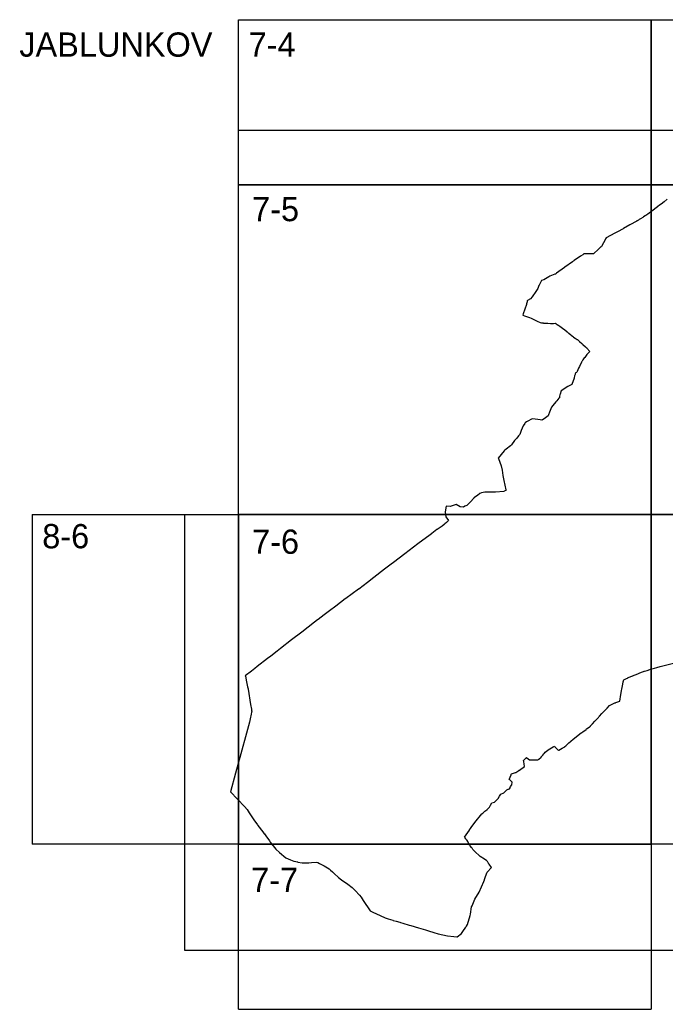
# Model space of a CAD drawing. Extents: x -449577 to -436680, y -1132317 to -1125726.
# Drawn here: x -437175.4 to -436931, y -1130193.4 to -1129818.4 of the extents above; entities that cross this region are included whole.
import ezdxf

# ---------------------------------------------------------------- set-up
doc = ezdxf.new("R2010")
doc.units = 0
for name, color, linetype in [('Vrstva 1', 7, 'Continuous'), ('Vrstva 10', 7, 'Continuous'), ('Vrstva 4', 7, 'Continuous')]:
    doc.layers.add(name, color=color, linetype=linetype)

msp = doc.modelspace()

# ---------------------------------------------------------------- linework, layer by layer
at = {"layer": 'Vrstva 1'}
for points in [[(-436930.19, -1129886.4), (-436931.4, -1129887.36), (-436931.4, -1129887.36), (-436932.55, -1129888.23), (-436933.12, -1129888.66), (-436933.7, -1129889.1), (-436933.86, -1129889.22), (-436935.99, -1129890.86), (-436937.06, -1129891.68), (-436937.53, -1129892.02), (-436938.29, -1129892.53), (-436938.54, -1129892.69), (-436939.13, -1129893.08), (-436939.17, -1129893.11), (-436939.38, -1129893.25), (-436940.29, -1129893.85), (-436940.3, -1129893.85), (-436940.77, -1129894.11), (-436940.92, -1129894.19), (-436941.1, -1129894.29), (-436941.56, -1129894.54), (-436941.74, -1129894.65), (-436941.9, -1129894.74), (-436942, -1129894.8), (-436942.24, -1129894.94), (-436943.9, -1129895.88), (-436944.07, -1129895.97), (-436944.3, -1129896.1), (-436946.77, -1129897.5), (-436946.89, -1129897.57), (-436949, -1129898.7), (-436950.02, -1129899.25), (-436953.36, -1129901.06), (-436953.53, -1129901.36), (-436953.59, -1129901.47), (-436954.37, -1129902.93), (-436955.05, -1129904.25), (-436955.19, -1129904.38), (-436955.28, -1129904.46), (-436956.42, -1129905.5), (-436957.93, -1129906.88), (-436958.1, -1129907.03), (-436958.1, -1129907.04), (-436958.57, -1129907.05), (-436961.76, -1129907.14), (-436961.77, -1129907.14), (-436962.2, -1129907.43), (-436963.03, -1129908), (-436965.5, -1129909.66), (-436965.54, -1129909.68), (-436965.78, -1129909.86), (-436966.05, -1129910.06), (-436969.03, -1129912.19), (-436969.1, -1129912.24), (-436972.1, -1129914.42), (-436972.57, -1129914.76), (-436972.73, -1129914.82), (-436974.67, -1129915.54), (-436974.68, -1129915.54), (-436975.07, -1129915.78), (-436976.95, -1129916.94), (-436977.87, -1129917.15), (-436978.12, -1129917.66), (-436978.88, -1129919.17), (-436978.89, -1129919.18), (-436978.96, -1129919.44), (-436979.16, -1129920.28), (-436979.99, -1129921.39), (-436981.36, -1129923.34), (-436981.92, -1129924.15), (-436981.95, -1129924.17), (-436983.11, -1129924.81), (-436983.21, -1129924.87), (-436983.28, -1129925.26), (-436983.43, -1129926.07), (-436983.48, -1129926.26), (-436984.77, -1129929.84), (-436984.94, -1129930.32), (-436984.91, -1129930.31), (-436984.89, -1129930.3), (-436984.21, -1129930.56), (-436982.4, -1129931.22), (-436981.78, -1129931.51), (-436979.49, -1129932.59), (-436979.47, -1129932.59), (-436978.31, -1129933.06), (-436977.84, -1129933.24), (-436977.81, -1129933.25), (-436977.38, -1129933.28), (-436977.24, -1129933.29), (-436977.02, -1129933.31), (-436975.42, -1129933.41), (-436974.38, -1129933.48), (-436973.33, -1129933.45), (-436972.49, -1129933.42), (-436972.48, -1129933.42), (-436972.2, -1129933.57), (-436971.83, -1129933.83), (-436971.28, -1129934.21), (-436970.89, -1129934.49), (-436969.33, -1129935.63), (-436969.16, -1129935.75), (-436968.05, -1129936.67), (-436967.66, -1129936.99), (-436967.48, -1129937.14), (-436966.73, -1129937.75), (-436966.46, -1129937.98), (-436965.86, -1129938.47), (-436965.64, -1129938.65), (-436965, -1129939.07), (-436964.25, -1129939.57), (-436964.22, -1129939.59), (-436963.46, -1129940.27), (-436962.58, -1129941.05), (-436962.14, -1129941.43), (-436961.13, -1129942.32), (-436960.87, -1129942.55), (-436960.82, -1129942.6), (-436960.72, -1129942.7), (-436960.71, -1129942.71), (-436960.62, -1129942.81), (-436960.59, -1129942.84), (-436959.54, -1129944.07), (-436959.55, -1129944.08), (-436959.99, -1129944.57), (-436960.05, -1129944.64), (-436960.62, -1129945.27), (-436961.44, -1129946.33), (-436961.61, -1129946.54), (-436962.17, -1129947.26), (-436962.47, -1129947.79), (-436962.49, -1129947.83), (-436962.5, -1129947.85), (-436962.63, -1129948.13), (-436963.43, -1129949.8), (-436963.74, -1129950.44), (-436964.36, -1129951.73), (-436964.47, -1129951.97), (-436964.48, -1129951.97), (-436964.52, -1129952), (-436964.81, -1129952.2), (-436964.89, -1129952.24), (-436964.94, -1129952.34), (-436965.03, -1129952.54), (-436965.12, -1129952.82), (-436965.29, -1129953.38), (-436965.3, -1129953.4), (-436965.42, -1129953.9), (-436965.44, -1129953.97), (-436965.43, -1129954.03), (-436965.42, -1129954.11), (-436965.42, -1129954.18), (-436965.43, -1129954.23), (-436966.31, -1129956.56), (-436966.33, -1129956.61), (-436966.35, -1129956.65), (-436966.36, -1129956.66), (-436967.06, -1129956.96), (-436967.31, -1129957.07), (-436967.78, -1129957.31), (-436970.39, -1129959), (-436970.39, -1129959), (-436970.76, -1129960.31), (-436970.84, -1129960.57), (-436970.95, -1129960.99), (-436971.01, -1129961.2), (-436971.01, -1129961.21), (-436971, -1129961.21), (-436970.83, -1129961.37), (-436970.84, -1129961.38), (-436971.2, -1129961.77), (-436972, -1129962.77), (-436972.01, -1129962.78), (-436972.22, -1129963.03), (-436972.22, -1129963.04), (-436972.34, -1129963.19), (-436973.5, -1129964.54), (-436974.04, -1129965.17), (-436974.8, -1129967.12), (-436975.18, -1129968.14), (-436975.31, -1129968.49), (-436976.84, -1129969.59), (-436977.46, -1129970.03), (-436977.64, -1129970.07), (-436977.66, -1129970.07), (-436978.29, -1129969.98), (-436981.13, -1129969.56), (-436981.62, -1129969.8), (-436982.95, -1129970.44), (-436983.49, -1129970.7), (-436983.52, -1129970.73), (-436983.95, -1129971.14), (-436984.12, -1129971.36), (-436984.78, -1129972.21), (-436984.78, -1129972.22), (-436985.45, -1129974.02), (-436986.02, -1129975.52), (-436986.02, -1129975.52), (-436986.16, -1129975.74), (-436986.49, -1129976.11), (-436987.21, -1129976.91), (-436987.91, -1129977.68), (-436987.92, -1129977.7), (-436988.05, -1129977.89), (-436989.12, -1129979.46), (-436989.59, -1129979.84), (-436991.16, -1129981.1), (-436991.83, -1129981.64), (-436991.93, -1129981.72), (-436991.96, -1129981.76), (-436993.08, -1129983.19), (-436994.22, -1129984.5), (-436994.07, -1129984.67), (-436994.06, -1129984.7), (-436994.06, -1129984.71), (-436993.05, -1129987.47), (-436992.77, -1129989.13), (-436992.45, -1129991.08), (-436992.04, -1129993.04), (-436991.31, -1129996.54), (-436991.27, -1129996.74), (-436991.92, -1129997.08), (-436992.04, -1129997.15), (-436995.21, -1129997.41), (-436995.37, -1129997.41), (-436996.86, -1129997.38), (-436999.25, -1129997.36), (-437000.53, -1129997.63), (-437001.13, -1129997.9), (-437002.11, -1129998.7), (-437003.41, -1129999.57), (-437003.5, -1129999.68), (-437004.66, -1130001.1), (-437006.11, -1130002.44), (-437006.8, -1130002.76), (-437007.4, -1130003.04), (-437008.57, -1130002.97), (-437010.18, -1130002.12), (-437012.42, -1130002.79), (-437013.9, -1130002.76), (-437014.28, -1130004.87), (-437014.29, -1130004.89), (-437014.3, -1130004.98), (-437014.01, -1130006.79), (-437013.04, -1130008.11), (-437013.03, -1130008.13), (-437013.77, -1130008.88), (-437014.38, -1130009.44), (-437014.63, -1130009.67), (-437015.43, -1130010.3), (-437017.36, -1130011.53), (-437017.42, -1130011.57), (-437019.39, -1130013.1), (-437019.45, -1130013.14), (-437019.94, -1130013.52), (-437024.6, -1130016.98), (-437024.63, -1130017.01), (-437029.58, -1130020.77), (-437033.84, -1130024.02), (-437034.72, -1130024.68), (-437037.29, -1130026.62), (-437041.29, -1130029.75), (-437043.73, -1130031.62), (-437047.04, -1130034.15), (-437047.09, -1130034.19), (-437051.88, -1130037.7), (-437052.11, -1130037.88), (-437055.72, -1130040.56), (-437058.11, -1130042.38), (-437060.08, -1130043.86), (-437062.4, -1130045.61), (-437062.63, -1130045.78), (-437063.76, -1130046.67), (-437068.58, -1130050.47), (-437072.47, -1130053.42), (-437076.69, -1130056.67), (-437077.98, -1130057.67), (-437080.37, -1130059.55), (-437081.55, -1130060.47), (-437085.49, -1130063.52), (-437086.42, -1130064.23), (-437087.66, -1130065.19), (-437089.98, -1130066.99), (-437089.98, -1130066.99), (-437089.94, -1130067.17), (-437089.65, -1130068.55), (-437089.62, -1130068.71), (-437089.09, -1130071.25), (-437088.93, -1130071.98), (-437088.93, -1130072.02), (-437088, -1130077.9), (-437087.99, -1130077.93), (-437087.69, -1130079.66), (-437087.69, -1130079.68), (-437087.63, -1130080.05), (-437087.57, -1130080.47), (-437087.6, -1130080.84), (-437087.75, -1130081.57), (-437088.13, -1130083.36), (-437088.42, -1130084.54), (-437088.44, -1130084.59), (-437089.55, -1130088.76), (-437091.65, -1130096.64), (-437093.64, -1130103.86), (-437095.57, -1130110.96), (-437095.58, -1130111), (-437090.3, -1130116.6), (-437089.25, -1130117.73), (-437088.49, -1130118.95), (-437086.47, -1130122.01), (-437086.42, -1130122.08), (-437085.41, -1130123.49), (-437085.25, -1130123.7), (-437083.37, -1130126.18), (-437082.8, -1130126.92), (-437082.77, -1130126.96), (-437082.25, -1130127.68), (-437080.87, -1130129.58), (-437080.54, -1130130.03), (-437078.39, -1130132.75), (-437076.99, -1130133.97), (-437074.59, -1130135.95), (-437072.85, -1130136.7), (-437071.66, -1130137.22), (-437071.53, -1130137.27), (-437070.2, -1130137.55), (-437070.06, -1130137.58), (-437068.44, -1130137.91), (-437068.41, -1130137.91), (-437067.45, -1130137.89), (-437067.07, -1130137.89), (-437066.55, -1130137.88), (-437065.87, -1130137.87), (-437064.96, -1130137.83), (-437063.01, -1130137.67), (-437062.56, -1130137.74), (-437061.9, -1130138.09), (-437060.18, -1130139.04), (-437058.22, -1130140.14), (-437057.7, -1130140.62), (-437056.98, -1130141.3), (-437056.18, -1130142.05), (-437054.86, -1130143.35), (-437054.72, -1130143.45), (-437053.53, -1130144.3), (-437051.12, -1130146.01), (-437049.48, -1130147.19), (-437048.43, -1130148.37), (-437046.79, -1130150.19), (-437046.15, -1130150.9), (-437045.79, -1130151.49), (-437045.33, -1130152.23), (-437044.39, -1130153.7), (-437043.76, -1130154.62), (-437042.72, -1130156.06), (-437041.65, -1130156.57), (-437040.27, -1130157.22), (-437038.96, -1130157.83), (-437036.99, -1130158.72), (-437035.86, -1130159.07), (-437034.14, -1130159.64), (-437033.99, -1130159.69), (-437032.9, -1130160.01), (-437031.48, -1130160.43), (-437031.47, -1130160.43), (-437031.26, -1130160.49), (-437031.2, -1130160.51), (-437030.34, -1130160.77), (-437027.95, -1130161.46), (-437027.83, -1130161.5), (-437027.35, -1130161.64), (-437024.42, -1130162.51), (-437021.73, -1130163.34), (-437021.39, -1130163.44), (-437020.63, -1130163.67), (-437018.62, -1130164.29), (-437016.89, -1130164.84), (-437013.43, -1130165.58)], [(-437013.43, -1130165.58), (-437011.04, -1130165.77), (-437009.84, -1130166), (-437009.73, -1130165.91), (-437008.15, -1130164.64), (-437007.12, -1130163.16), (-437007.01, -1130163.01), (-437006.49, -1130162.25), (-437006.38, -1130162.08), (-437006.24, -1130161.85), (-437005.86, -1130161.22), (-437005.59, -1130160.39), (-437005.57, -1130160.32), (-437005.55, -1130160.27), (-437005.52, -1130160.16), (-437005.49, -1130160.07), (-437005.49, -1130160.06), (-437004.86, -1130157.86), (-437004.72, -1130157.34), (-437004.27, -1130154.59), (-437004.27, -1130154.59), (-437004.08, -1130154.15), (-437003.82, -1130153.53), (-437003.03, -1130151.7), (-437001.46, -1130149.05), (-436999.71, -1130144.92), (-436999.39, -1130144.28), (-436999.35, -1130144.15), (-436998.96, -1130143.05), (-436998.37, -1130141.38), (-436996.69, -1130139.67), (-436997.62, -1130138.43), (-436997.68, -1130138.34), (-436997.73, -1130138.28), (-436997.76, -1130138.24), (-436997.83, -1130138.14), (-436997.88, -1130138.06), (-436997.96, -1130137.94), (-436998.32, -1130137.42), (-436998.69, -1130136.96), (-436999.26, -1130136.59), (-436999.36, -1130136.53), (-437001.01, -1130135.46), (-437003.2, -1130133.52), (-437003.33, -1130133.35), (-437003.36, -1130133.31), (-437003.44, -1130133.21), (-437003.78, -1130132.79), (-437004.11, -1130132.38), (-437004.37, -1130132.06), (-437004.85, -1130131.47), (-437004.93, -1130131.37), (-437005.43, -1130130.41), (-437005.72, -1130129.85), (-437005.95, -1130129.42), (-437006, -1130129.33), (-437006.04, -1130129.28), (-437006.3, -1130128.99), (-437006.5, -1130128.76), (-437006.76, -1130128.47), (-437006.98, -1130128.22), (-437005.12, -1130125.48), (-437005.03, -1130125.36), (-437004.71, -1130124.91), (-437004.39, -1130124.47), (-437003.06, -1130122.64), (-437000.38, -1130119.38), (-437000.03, -1130119.06), (-436999.32, -1130118.36), (-436999.21, -1130118.27), (-436999.02, -1130118.13), (-436998.42, -1130117.65), (-436997.56, -1130116.81), (-436997.15, -1130116.05), (-436996.68, -1130115.18), (-436995.63, -1130114.94), (-436994.23, -1130113.51), (-436993.69, -1130112.66), (-436993.68, -1130112.65), (-436993.68, -1130112.63), (-436993.47, -1130112.3), (-436993.42, -1130112.22), (-436993.18, -1130111.83), (-436992.02, -1130111.39), (-436991, -1130110.21), (-436990.47, -1130110.01), (-436990.35, -1130109.96), (-436989.93, -1130109.8), (-436989.71, -1130109.41), (-436989.66, -1130109.32), (-436989.49, -1130109.02), (-436989.08, -1130108.28), (-436988.88, -1130107.37), (-436988.88, -1130107.35), (-436988.87, -1130107.34), (-436989.92, -1130106.35), (-436989.94, -1130106.34), (-436989.95, -1130106.32), (-436990, -1130106.28), (-436989.35, -1130104.48), (-436989.28, -1130104.28), (-436989.12, -1130104.22), (-436988.39, -1130103.93), (-436987.7, -1130103.66), (-436987.58, -1130103.61), (-436986.37, -1130102.9), (-436986.25, -1130102.82), (-436986.25, -1130102.82), (-436986.24, -1130102.81), (-436986.12, -1130102.74), (-436984.26, -1130101.34), (-436984.26, -1130101.3), (-436984.29, -1130101.14), (-436984.36, -1130100.66), (-436984.42, -1130100.31), (-436984.52, -1130099.69), (-436984.54, -1130099.58), (-436984.56, -1130099.45), (-436984.58, -1130099.28), (-436984.61, -1130099.14), (-436984.07, -1130098.58), (-436983.51, -1130098.01), (-436983.47, -1130097.96), (-436983.33, -1130098.06), (-436982.33, -1130098.85), (-436981.65, -1130098.86), (-436981.59, -1130098.86), (-436981.34, -1130098.87), (-436981.18, -1130098.87), (-436979.87, -1130098.89), (-436979.24, -1130098.91), (-436978.97, -1130098.75), (-436978.94, -1130098.73), (-436978.82, -1130098.66), (-436978.68, -1130098.57), (-436978.64, -1130098.54), (-436978.1, -1130097.94), (-436977.99, -1130097.82), (-436977.9, -1130097.72), (-436977.73, -1130097.54), (-436977.65, -1130097.45), (-436977.54, -1130097.33), (-436977.51, -1130097.29), (-436977.48, -1130097.26), (-436977.43, -1130097.2), (-436977.34, -1130097.09), (-436976.94, -1130096.59), (-436976.73, -1130096.33), (-436976.48, -1130096.01), (-436976.37, -1130095.93), (-436974.91, -1130094.86), (-436974.7, -1130094.73), (-436973.34, -1130093.96), (-436972.94, -1130093.73), (-436972.94, -1130093.73), (-436972.8, -1130093.88), (-436972.09, -1130094.59), (-436971.72, -1130094.97), (-436971.54, -1130095.14), (-436971.39, -1130095.29), (-436971.3, -1130095.25), (-436970.02, -1130094.48), (-436969.93, -1130094.43), (-436969, -1130093.87), (-436968.96, -1130093.84), (-436968.63, -1130093.55), (-436968.58, -1130093.51), (-436968.41, -1130093.36), (-436968.4, -1130093.35), (-436968.4, -1130093.35), (-436968.36, -1130093.31), (-436968.32, -1130093.27), (-436967.43, -1130092.46), (-436967.41, -1130092.45), (-436966.82, -1130091.91), (-436966.71, -1130091.82), (-436966.6, -1130091.72), (-436966.6, -1130091.72), (-436966.59, -1130091.72), (-436966.59, -1130091.72), (-436966.59, -1130091.71), (-436966.58, -1130091.71), (-436966.57, -1130091.7), (-436966.57, -1130091.7), (-436966.56, -1130091.69), (-436966.56, -1130091.69), (-436966.55, -1130091.69), (-436966.55, -1130091.69), (-436965.97, -1130091.2), (-436963.98, -1130089.52), (-436962.78, -1130088.67), (-436962.66, -1130088.59), (-436962.61, -1130088.55), (-436962.59, -1130088.54), (-436962.54, -1130088.51), (-436962.18, -1130088.24), (-436960.94, -1130087.3), (-436960.76, -1130087.16), (-436960.55, -1130087), (-436960.53, -1130086.98), (-436959.65, -1130086.31), (-436959.3, -1130086.04), (-436959.25, -1130085.98), (-436959.16, -1130085.88), (-436958.52, -1130085.2), (-436957.62, -1130084.22), (-436956.26, -1130082.81), (-436956.04, -1130082.58), (-436955.79, -1130082.3), (-436954.95, -1130081.35), (-436954.66, -1130081.03), (-436954.46, -1130080.82), (-436954.17, -1130080.5), (-436952.99, -1130079.31), (-436952.06, -1130078.29), (-436950, -1130077.28), (-436949.84, -1130077.23), (-436949.64, -1130077.15), (-436948.2, -1130076.66), (-436948.05, -1130075.79), (-436947.89, -1130074.92), (-436947.47, -1130072.55), (-436947.39, -1130072.08), (-436947.06, -1130070.2), (-436946.86, -1130069.32), (-436946.83, -1130069.2), (-436946.78, -1130069.01), (-436946.77, -1130068.97), (-436946.75, -1130068.9), (-436946.74, -1130068.86), (-436946.73, -1130068.81), (-436946.72, -1130068.77), (-436946.71, -1130068.75), (-436946.65, -1130068.54), (-436945.57, -1130068), (-436945.28, -1130067.86), (-436945.26, -1130067.85), (-436945.01, -1130067.72), (-436944.96, -1130067.7), (-436943.19, -1130066.98), (-436943.16, -1130066.97), (-436943.13, -1130066.95), (-436942.33, -1130066.64), (-436941.37, -1130066.24), (-436940.56, -1130065.9), (-436939.62, -1130065.51), (-436939.54, -1130065.48), (-436938.93, -1130065.24), (-436939.08, -1130065.4), (-436938.84, -1130065.31), (-436938.35, -1130065.11), (-436937.82, -1130064.95), (-436936.12, -1130064.43), (-436935.53, -1130064.26), (-436935.08, -1130064.14), (-436934.19, -1130063.89), (-436932.88, -1130063.51), (-436931.34, -1130063.05), (-436927.8, -1130062.18)]]:
    msp.add_lwpolyline(points, dxfattribs=at)
at = {"layer": 'Vrstva 10'}
msp.add_lwpolyline([(-436780.04, -1129860.19), (-436780.04, -1130171.17), (-437112.91, -1130171.17), (-437112.91, -1130005.87), (-437092.54, -1130005.87), (-437092.54, -1129880.87), (-437092.54, -1129860.19), (-436780.04, -1129860.19)], dxfattribs=at)
at = {"layer": 'Vrstva 4'}
for p, q in [((-437092.54, -1129818.37), (-436780.04, -1129818.37)), ((-437170.67, -1130005.87), (-437170.67, -1130130.87)), ((-437092.54, -1130193.37), (-436936.29, -1130193.37))]:
    msp.add_line(p, q, dxfattribs=at)
for points in [[(-436936.29, -1129818.37), (-436936.29, -1129880.87), (-437092.54, -1129880.87), (-437092.54, -1129818.37)], [(-436780.04, -1129818.37), (-436780.04, -1129880.87), (-436936.29, -1129880.87), (-436936.29, -1129818.37)], [(-437170.67, -1130005.87), (-437092.54, -1130005.87), (-437092.54, -1130130.87), (-437170.67, -1130130.87)], [(-437092.54, -1130193.37), (-437092.54, -1130130.87), (-436936.29, -1130130.87), (-436936.29, -1130193.37)]]:
    msp.add_lwpolyline(points, dxfattribs=at)
for points in [[(-436936.29, -1129880.87), (-436936.29, -1130005.87), (-437092.54, -1130005.87), (-437092.54, -1129880.87)], [(-436780.04, -1129880.87), (-436780.04, -1130005.87), (-436936.29, -1130005.87), (-436936.29, -1129880.87)], [(-436936.29, -1130005.87), (-436936.29, -1130130.87), (-437092.54, -1130130.87), (-437092.54, -1130005.87)], [(-436780.04, -1130005.87), (-436780.04, -1130130.87), (-436936.29, -1130130.87), (-436936.29, -1130005.87)]]:
    msp.add_lwpolyline(points, close=True, dxfattribs=at)

# ---------------------------------------------------------------- texts
at = {"layer": 'Vrstva 1'}
for s, p in [('JABLUNKOV', (-437175.58, -1129832.37)), ('7-4', (-437088.73, -1129832.37)), ('7-5', (-437087.42, -1129894.71)), ('8-6', (-437166.89, -1130018.68)), ('7-6', (-437087.42, -1130020.78)), ('7-7', (-437087.78, -1130148.95))]:
    msp.add_text(s, height=9.2, dxfattribs=at).set_placement(p)

doc.saveas('drawing.dxf')
